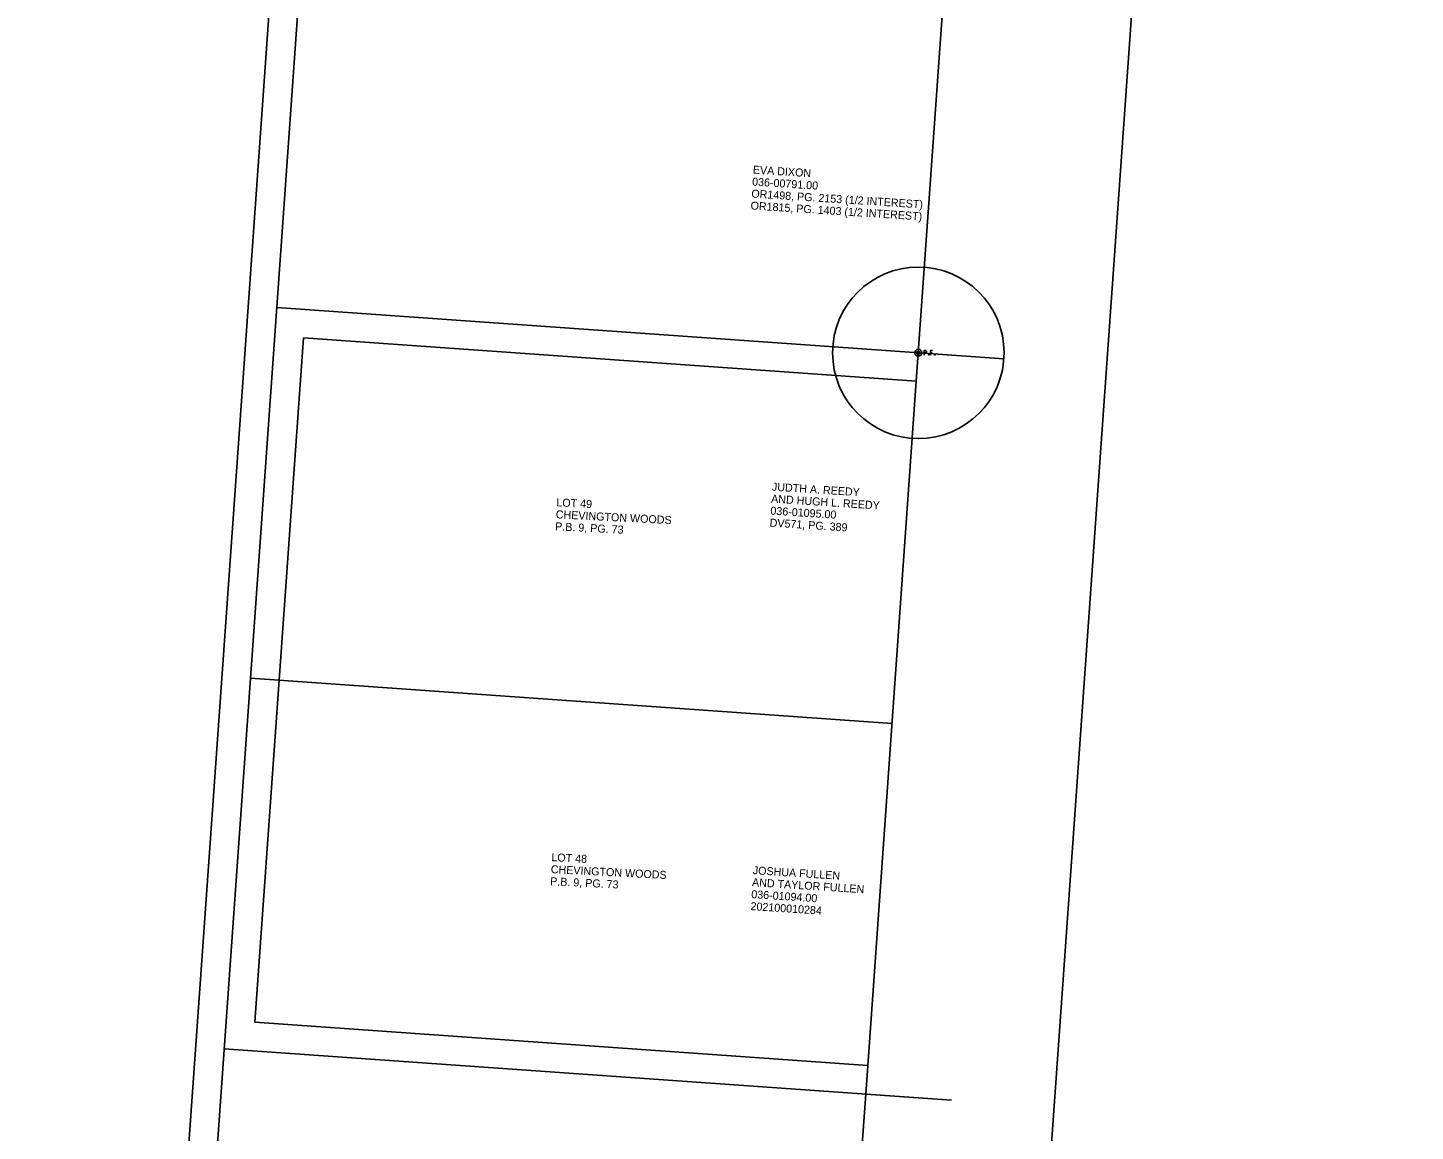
# Model space of a CAD drawing. Extents: x 1898254 to 1901377, y 701554 to 704886.
# Drawn here: x 1899435.4 to 1899920.8, y 702411 to 702797.1 of the extents above; entities that cross this region are included whole.
import ezdxf

# ---------------------------------------------------------------- set-up
doc = ezdxf.new("R2010")
doc.units = 0
for name, color, linetype in [('DV_X_Property_Line', 7, 'Continuous'), ('DV_X_Text', 7, 'Continuous'), ('RW_X_Esmt_General', 7, 'Continuous'), ('RW_X_Esmt_SH', 7, 'Continuous'), ('RW_X_Fee_RW', 7, 'Continuous'), ('SC_Scratch1', 7, 'Continuous'), ('SC_Scratch2', 7, 'Continuous'), ('SV_X_Mon_Cells_Found', 7, 'Continuous')]:
    doc.layers.add(name, color=color, linetype=linetype)

msp = doc.modelspace()

# ---------------------------------------------------------------- linework, layer by layer
at = {"layer": 'DV_X_Property_Line'}
for p, q in [((1899476.33, 702046.99), (1899540.91, 702958.62)), ((1899522.54, 702699.25), (1899776.9, 702681.23)), ((1899513.35, 702569.58), (1899737.79, 702553.68)), ((1899504.16, 702439.9), (1899758.53, 702421.88))]:
    msp.add_line(p, q, dxfattribs=at)
at = {"layer": 'RW_X_Esmt_General'}
for p, q in [((1899466.62, 702051.43), (1899530.23, 702949.35)), ((1899514.85, 702449.17), (1899531.81, 702688.57)), ((1899531.81, 702688.57), (1899746.27, 702673.38)), ((1899514.85, 702449.17), (1899729.31, 702433.98))]:
    msp.add_line(p, q, dxfattribs=at)
at = {"layer": 'RW_X_Esmt_SH'}
for p, q in [((1899746.97, 702683.35), (1899756.17, 702813.12)), ((1899708.11, 702134.73), (1899728.6, 702424))]:
    msp.add_line(p, q, dxfattribs=at)
at = {"layer": 'RW_X_Fee_RW'}
for p, q in [((1899745.58, 701729.7), (1899846.72, 703157.34)), ((1899728.6, 702424), (1899746.97, 702683.35)), ((1899728.6, 702424), (1899758.53, 702421.88))]:
    msp.add_line(p, q, dxfattribs=at)
at = {"layer": 'SC_Scratch1'}
msp.add_circle((1899746.97, 702683.35), 30, dxfattribs=at)
at = {"layer": 'SC_Scratch2'}
msp.add_circle((1899815.76, 703229.84), 1561.35, dxfattribs=at)
at = {"layer": 'SV_X_Mon_Cells_Found'}
for points in [[(1899748.97, 702682.55), (1899748.97, 702684.15), (1899749.5, 702684.15), (1899749.56, 702684.14), (1899749.63, 702684.12), (1899749.67, 702684.09), (1899749.7, 702684.07), (1899749.74, 702684), (1899749.78, 702683.94), (1899749.8, 702683.84), (1899749.8, 702683.69), (1899749.79, 702683.64), (1899749.77, 702683.56), (1899749.72, 702683.47), (1899749.68, 702683.44), (1899749.64, 702683.41), (1899749.59, 702683.39), (1899749.5, 702683.37), (1899748.97, 702683.37)], [(1899750.61, 702682.77), (1899750.67, 702682.77), (1899750.7, 702682.74), (1899750.74, 702682.69), (1899750.74, 702682.63), (1899750.7, 702682.58), (1899750.67, 702682.55), (1899750.61, 702682.55), (1899750.58, 702682.58), (1899750.55, 702682.63), (1899750.55, 702682.69), (1899750.58, 702682.74), (1899750.61, 702682.77)], [(1899751.98, 702684.15), (1899751.22, 702684.15), (1899751.22, 702682.55)], [(1899751.22, 702683.37), (1899751.76, 702683.37)], [(1899752.76, 702682.77), (1899752.82, 702682.77), (1899752.85, 702682.74), (1899752.88, 702682.69), (1899752.88, 702682.63), (1899752.85, 702682.58), (1899752.82, 702682.55), (1899752.76, 702682.55), (1899752.73, 702682.58), (1899752.7, 702682.63), (1899752.7, 702682.69), (1899752.73, 702682.74), (1899752.76, 702682.77)]]:
    msp.add_lwpolyline(points, dxfattribs=at)
for radius in [1.2, 0.495]:
    msp.add_circle((1899746.97, 702683.35), radius, dxfattribs=at)

# ---------------------------------------------------------------- texts
at = {"layer": 'DV_X_Text'}
for s, rotation, p in [('EVA DIXON', 356.3351, (1899689.01, 702746.07)), ('036-00791.00', 356.3351, (1899688.75, 702741.88)), ('OR1498, PG. 2153 (1/2 INTEREST)', 356.3351, (1899688.48, 702737.69)), ('OR1815, PG. 1403 (1/2 INTEREST)', 356.3351, (1899688.21, 702733.5)), ('JUDTH A. REEDY', 356.3351, (1899695.68, 702635.15)), ('LOT 49', 357.0949, (1899620.28, 702629.66)), ('AND HUGH L. REEDY', 356.3351, (1899695.41, 702630.96)), ('CHEVINGTON WOODS', 357.0949, (1899620.07, 702625.47)), ('036-01095.00', 356.3351, (1899695.14, 702626.77)), ('P.B. 9, PG. 73', 357.0949, (1899619.85, 702621.27)), ('DV571, PG. 389', 356.3351, (1899694.88, 702622.58)), ('LOT 48', 357.0949, (1899618.54, 702505.53)), ('CHEVINGTON WOODS', 357.0949, (1899618.33, 702501.33)), ('JOSHUA FULLEN', 356.3351, (1899688.99, 702500.98)), ('P.B. 9, PG. 73', 357.0949, (1899618.11, 702497.14)), ('AND TAYLOR FULLEN', 356.3351, (1899688.72, 702496.79)), ('202100010284', 356.3351, (1899688.19, 702488.41)), ('036-01094.00', 356.3351, (1899688.46, 702492.6))]:
    msp.add_text(s, height=2.8, rotation=rotation, dxfattribs=at).set_placement(p)

doc.saveas('drawing.dxf')
